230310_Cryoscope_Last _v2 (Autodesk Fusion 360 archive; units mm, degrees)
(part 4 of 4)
sketch "Sketch3" plane through (0, 0, 0) normal (0, 0, -1) x axis (1, 0, 0)
  line L1 (1.15, 0) -> (0, 0)
  circle C1 centre (0, 0) radius 3
  circle C2 centre (-1.5, 0) radius 0.35
  circle C3 centre (1.5, 0) radius 0.35
  arc A1 centre (0, 0) radius 1.5 clockwise from (1.4592, -0.3476) to (1.4592, 0.3476)
  point P1 (0, 0)
  point P3 (0, 0)
  point P4 (-1.5, 0)
  point P5 (0, 0)
  point P7 (1.4592, 0.3476)
  point P8 (1.15, 0)
  point P9 (1.4592, -0.3476)
  coincident P1 P3
  coincident P4 A1
  coincident P1 P5
  horizontal L1
  coincident C3 P7
  coincident C3 P8
  coincident C3 P9
  dimension "d8" diameter A1 = 3
  dimension "d9" diameter C2 = 0.7
  dimension "d10" diameter C3 = 0.7
extrude "Extrude3" add sketch "Sketch3" profile of A1 C2 C3 along normal blind 10
extrude "Extrude4" add of existing geometry blind 10
split "Split1"

design "Lumatec 3 mm LLG"
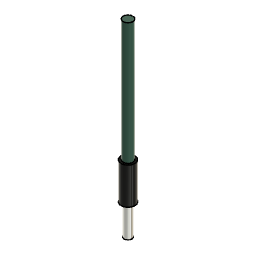
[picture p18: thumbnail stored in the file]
sketch "Sketch1" plane through (0, 0, 0) normal (0, 0, 1) x axis (1, 0, 0)
  circle C1 centre (0, 0) radius 2.46
  point P1 (0, 0)
  point P2 (0, 0)
  coincident P1 P2
  dimension "d1" diameter C1 = 4.92
extrude "Extrude1" new body sketch "Sketch1" along normal blind 20
sketch "Sketch2" plane through (0, 0, 0) normal (0, 0, -1) x axis (1, 0, 0)
  circle C1 centre (0, 0) radius 2.46
  circle C2 centre (0, 0) radius 1.5
  point P1 (0, 0)
  point P3 (0, 0)
  coincident P1 P3
  dimension "d4" diameter C2 = 3
sketch "Sketch3" plane through (0, 0, 0) normal (0, 0, -1) x axis (1, 0, 0)
  circle C1 centre (0, 0) radius 2.46
  circle C2 centre (0, 0) radius 1.5
  concentric C1 C2
  dimension "d7" diameter C2 = 3
extrude "Extrude3" cut sketch "Sketch3" profile of C2 against normal blind 31
extrude "Extrude4" new body sketch "Sketch2" profile of C2 against normal blind 20
sketch "Sketch4" plane through (0, 0, 20) normal (0, 0, 1) x axis (-1, 0, 0)
  circle C1 centre (0, 0) radius 1.5
  circle C2 centre (0, 0) radius 2.46
  circle C3 centre (0, 0) radius 4.475
  concentric C1 C3
  dimension "d12" diameter C3 = 8.95
extrude "Extrude5" new body sketch "Sketch4" along normal blind 24
extrude "Extrude6" add of existing geometry blind 24
sketch "Sketch5" plane through (0, 0, 44) normal (0, 0, 1) x axis (-1, 0, 0)
  circle C1 centre (0, 0) radius 1.5
  circle C2 centre (0, 0) radius 4.475
  circle C3 centre (0, 0) radius 3.1623
  point P1 (0, 0)
  point P3 (0, 0)
  coincident P1 P3
extrude "Extrude7" new body sketch "Sketch5" profile of C1 C3 along normal blind 80
extrude "Extrude8" add of existing geometry blind 0.1

design "Zeiss_dovetail"
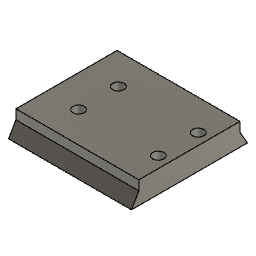
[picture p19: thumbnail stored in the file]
sketch "Sketch1" plane through (0, 0, 0) normal (1, 0, 0) x axis (0, 1, 0)
  line L1 (72.6, 0) -> (0, 0)
  line L2 (72.6, -11) -> (72.6, 0)
  line L3 (72.6, -3) -> (72.6, -11)
  line L4 (0, -11) -> (72.6, -11)
  line L5 (0, -3) -> (72.6, -3)
  line L6 (0, -11) -> (0, -3)
  line L7 (72.6, -11) -> (0, -11)
  line L8 (72.6, -3) -> (72.6, -11)
  line L9 (0, 0) -> (0, -3)
  line L10 (4.6188, -3) -> (0, -11)
  line L11 (9.2376, -11) -> (0, -11)
  line L12 (67.9812, -3) -> (72.6, -11)
  line L13 (78.8376, -11) -> (72.6, -11)
  line L14 (4.6188, 0) -> (4.6188, -3)
  line L15 (67.9812, 0) -> (67.9812, -3)
  point P1 (0, 0)
  point P2 (0, 0)
  point P9 (0, 0)
  point P10 (4.6188, -3)
  point P12 (67.9812, -3)
  point P14 (4.6188, 0)
  point P15 (67.9812, 0)
  point P3 (72.6, 0)
  point P4 (72.6, -11)
  point P5 (72.6, -3)
  coincident P1 P2
  horizontal L1
  perpendicular L1 L2
  perpendicular L1 L3
  perpendicular L3 L4
  horizontal L5
  vertical L6
  horizontal L7
  vertical L8
  coincident P1 P9
  perpendicular L1 L9
  horizontal L11
  coincident L5 P10
  horizontal L13
  coincident L5 P12
  coincident L1 P14
  perpendicular L1 L14
  coincident L1 P15
  perpendicular L1 L15
  dimension "d1" distance P2 P3 = 72.6
  dimension "d2" distance P3 P4 = 11
  dimension "d3" distance P4 P5 = 8
  dimension "d4" angle L10 L11 = 60
  dimension "d5" angle L12 L13 = 120
extrude "Extrude1" new body sketch "Sketch1" profile of L1 L4 L5 L7 L10 L12 L14 L15 along normal blind 70
sketch "Sketch2" plane through (0, 0, -11) normal (0, 0, -1) x axis (1, 0, 0)
  line L1 (0, -72.6) -> (0, 0)
  line L2 (70, -72.6) -> (0, -72.6)
  line L3 (70, 0) -> (70, -72.6)
  line L4 (0, 0) -> (70, 0)
  line L5 (70, -72.6) -> (70, 0)
  line L6 (0, -36.3) -> (70, -36.3)
  line L7 (70, -23.8) -> (70, -36.3)
  line L8 (0, -23.8) -> (70, -23.8)
  line L9 (70, -48.8) -> (70, -36.3)
  line L10 (0, -48.8) -> (70, -48.8)
  line L11 (60, -36.3) -> (35, -36.3)
  line L12 (10, -36.3) -> (35, -36.3)
  line L13 (10, -48.8) -> (10, -36.3)
  line L14 (10, -23.8) -> (10, -36.3)
  line L15 (60, -23.8) -> (60, -36.3)
  line L16 (60, -48.8) -> (60, -36.3)
  circle C1 centre (60, -48.8) radius 3.5
  circle C2 centre (60, -23.8) radius 3.5
  circle C3 centre (10, -48.8) radius 3.5
  circle C4 centre (10, -23.8) radius 3.5
  point P5 (70, 0)
  point P6 (70, 0)
  point P4 (70, -72.6)
  point P7 (70, -72.6)
  point P8 (70, -36.3)
  point P9 (0, -36.3)
  point P11 (0, -23.8)
  point P12 (70, -48.8)
  point P13 (0, -48.8)
  point P14 (35, -36.3)
  point P17 (10, -48.8)
  point P18 (10, -23.8)
  point P19 (60, -23.8)
  point P20 (60, -48.8)
  point P21 (60, -48.8)
  point P22 (60, -23.8)
  point P23 (10, -48.8)
  point P24 (10, -23.8)
  point P10 (70, -23.8)
  point P15 (60, -36.3)
  point P16 (10, -36.3)
  coincident P5 P6
  coincident P4 P7
  midpoint L5 P8
  midpoint L1 P9
  perpendicular L6 L7
  coincident L1 P11
  perpendicular L1 L8
  coincident L5 P12
  coincident L1 P13
  perpendicular L1 L10
  midpoint L6 P14
  parallel L6 L11
  parallel L6 L12
  coincident L10 P17
  perpendicular L10 L13
  coincident L8 P18
  perpendicular L8 L14
  coincident L8 P19
  perpendicular L8 L15
  coincident L10 P20
  perpendicular L10 L16
  coincident P20 P21
  coincident P19 P22
  coincident P17 P23
  coincident P18 P24
  dimension "d8" distance P8 P10 = 12.5
  dimension "d9" distance P8 P12 = 12.5
  dimension "d10" distance P14 P15 = 25
  dimension "d11" distance P14 P16 = 25
  dimension "d12" diameter C1 = 7
  dimension "d13" diameter C2 = 7
  dimension "d14" diameter C3 = 7
  dimension "d15" diameter C4 = 7
extrude "Extrude2" cut sketch "Sketch2" profile of L8 L10 L13 L14 L15 L16 C1 C2 C3 C4 against normal blind 100
sketch "Sketch3" plane through (0, 0, -11) normal (0, 0, -1) x axis (1, 0, 0)
  line L1 (0, -72.6) -> (0, 0)
  line L2 (70, -72.6) -> (0, -72.6)
  line L3 (70, 0) -> (70, -72.6)
  line L4 (0, 0) -> (70, 0)
  circle C1 centre (60, -48.8) radius 3.5
  circle C2 centre (10, -48.8) radius 3.5
  circle C3 centre (60, -23.8) radius 3.5
  circle C4 centre (10, -23.8) radius 3.5
  circle C5 centre (60, -23.8) radius 5
  circle C6 centre (60, -48.8) radius 5
  circle C7 centre (10, -48.8) radius 5
  circle C8 centre (10, -23.8) radius 5
  concentric C3 C5
  concentric C1 C6
  concentric C2 C7
  concentric C4 C8
  dimension "d18" diameter C5 = 10
  dimension "d19" diameter C6 = 10
  dimension "d20" diameter C7 = 10
  dimension "d21" diameter C8 = 10
extrude "Extrude3" cut sketch "Sketch3" profile of C1 C2 C3 C4 C5 C6 C7 C8 against normal blind 6
extrude "Extrude4" add of existing geometry blind 10
extrude "Extrude5" add of existing geometry blind 10
extrude "Extrude6" cut of existing geometry blind -13
extrude "Extrude7" add of existing geometry blind 3

design "PH50E_M-Step"
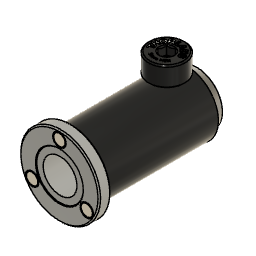
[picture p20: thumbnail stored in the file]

design "C60-TUBE-B (CATALOG MODEL)"
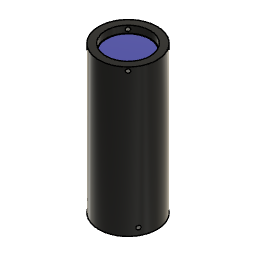
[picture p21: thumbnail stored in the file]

design "USB_A_FEM" references "BOOMELE(Boom Precision Elec) C32896"
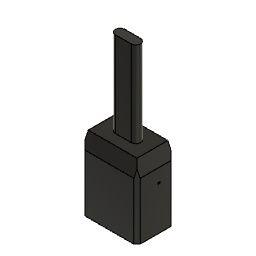
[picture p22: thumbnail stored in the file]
component_insert "Component Insert"
sketch "Sketch1" plane through (0, 0, 0) normal (0, 0, -1) x axis (1, 0, 0)
  line L1 (-6.75, 1.85) -> (-6.55, 1.85)
  line L2 (-7.15, -1.45) -> (-7.15, 1.45)
  line L3 (-6.55, -1.85) -> (-6.75, -1.85)
  line L4 (-6.55, -2.45) -> (-6.55, -1.85)
  line L5 (-5.65, -2.85) -> (-6.15, -2.85)
  line L6 (-5.65, -2.95) -> (-5.65, -2.85)
  line L7 (5.25, -3.35) -> (-5.25, -3.35)
  line L8 (5.65, -2.85) -> (5.65, -2.95)
  line L9 (6.15, -2.85) -> (5.65, -2.85)
  line L10 (6.55, -1.85) -> (6.55, -2.45)
  line L11 (6.75, -1.85) -> (6.55, -1.85)
  line L12 (7.15, 1.45) -> (7.15, -1.45)
  line L13 (6.55, 1.85) -> (6.75, 1.85)
  line L14 (6.55, 2.45) -> (6.55, 1.85)
  line L15 (5.65, 2.85) -> (6.15, 2.85)
  line L16 (5.65, 2.95) -> (5.65, 2.85)
  line L17 (-5.25, 3.35) -> (5.25, 3.35)
  line L18 (-5.65, 2.85) -> (-5.65, 2.95)
  line L19 (-6.15, 2.85) -> (-5.65, 2.85)
  line L20 (-6.55, 1.85) -> (-6.55, 2.45)
  line L21 (6.15, -2.05) -> (6.15, 2.05)
  line L22 (-5.75, -2.45) -> (5.75, -2.45)
  line L23 (-6.15, 2.05) -> (-6.15, -2.05)
  line L24 (5.75, 2.45) -> (-5.75, 2.45)
  line L25 (-8.7, 5.85) -> (8.7, 5.85)
  line L26 (-8.7, -5.85) -> (-8.7, 5.85)
  line L27 (8.7, -5.85) -> (-8.7, -5.85)
  line L28 (8.7, 5.85) -> (8.7, -5.85)
  line L29 (-8.7, -5.85) -> (8.7, 5.85)
  line L30 (8.7, -5.85) -> (-8.7, 5.85)
  arc A1 centre (-6.75, 1.45) radius 0.4 clockwise from (-7.15, 1.45) to (-6.75, 1.85)
  arc A2 centre (-6.75, -1.45) radius 0.4 clockwise from (-6.75, -1.85) to (-7.15, -1.45)
  arc A3 centre (-6.15, -2.45) radius 0.4 clockwise from (-6.15, -2.85) to (-6.55, -2.45)
  arc A4 centre (-5.25, -2.95) radius 0.4 clockwise from (-5.25, -3.35) to (-5.65, -2.95)
  arc A5 centre (5.25, -2.95) radius 0.4 clockwise from (5.65, -2.95) to (5.25, -3.35)
  arc A6 centre (6.15, -2.45) radius 0.4 clockwise from (6.55, -2.45) to (6.15, -2.85)
  arc A7 centre (6.75, -1.45) radius 0.4 clockwise from (7.15, -1.45) to (6.75, -1.85)
  arc A8 centre (6.75, 1.45) radius 0.4 clockwise from (6.75, 1.85) to (7.15, 1.45)
  arc A9 centre (6.15, 2.45) radius 0.4 clockwise from (6.15, 2.85) to (6.55, 2.45)
  arc A10 centre (5.25, 2.95) radius 0.4 clockwise from (5.25, 3.35) to (5.65, 2.95)
  arc A11 centre (-5.25, 2.95) radius 0.4 clockwise from (-5.65, 2.95) to (-5.25, 3.35)
  arc A12 centre (-6.15, 2.45) radius 0.4 clockwise from (-6.55, 2.45) to (-6.15, 2.85)
  arc A13 centre (5.75, -2.05) radius 0.4 clockwise from (6.15, -2.05) to (5.75, -2.45)
  arc A14 centre (-5.75, -2.05) radius 0.4 clockwise from (-5.75, -2.45) to (-6.15, -2.05)
  arc A15 centre (-5.75, 2.05) radius 0.4 clockwise from (-6.15, 2.05) to (-5.75, 2.45)
  arc A16 centre (5.75, 2.05) radius 0.4 clockwise from (5.75, 2.45) to (6.15, 2.05)
  point P62 (0, 0)
  point P1 (0, 0)
  point P60 (-8.7, -5.85)
  point P61 (8.7, -5.85)
  point P59 (-8.7, 5.85)
  horizontal L25
  perpendicular L25 L26
  parallel L25 L27
  parallel L26 L28
  coincident L29 P62
  coincident L30 P62
  coincident P1 P62
  dimension "d1" distance P60 P61 = 17.4
  dimension "d2" distance P59 P60 = 11.7
extrude "Extrude1" new body sketch "Sketch1" profile of L1 A1 L2 A2 L3 L4 A3 L5 L6 A4 L7 A5 L8 L9 A6 L10 L11 A7 L12 A8 L13 L14 A9 L15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 against normal blind 18
sketch "Sketch2" plane through (0, 0, 18) normal (0, 0, 1) x axis (-1, 0, 0)
  line L1 (6.55, 1.85) -> (6.55, 2.45)
  line L2 (6.75, 1.85) -> (6.55, 1.85)
  line L3 (7.15, -1.45) -> (7.15, 1.45)
  line L4 (6.55, -1.85) -> (6.75, -1.85)
  line L5 (6.55, -2.45) -> (6.55, -1.85)
  line L6 (5.65, -2.85) -> (6.15, -2.85)
  line L7 (5.65, -2.95) -> (5.65, -2.85)
  line L8 (-5.25, -3.35) -> (5.25, -3.35)
  line L9 (-5.65, -2.85) -> (-5.65, -2.95)
  line L10 (-6.15, -2.85) -> (-5.65, -2.85)
  line L11 (-6.55, -1.85) -> (-6.55, -2.45)
  line L12 (-6.75, -1.85) -> (-6.55, -1.85)
  line L13 (-7.15, 1.45) -> (-7.15, -1.45)
  line L14 (-6.55, 1.85) -> (-6.75, 1.85)
  line L15 (-6.55, 2.45) -> (-6.55, 1.85)
  line L16 (-5.65, 2.85) -> (-6.15, 2.85)
  line L17 (-5.65, 2.95) -> (-5.65, 2.85)
  line L18 (5.25, 3.35) -> (-5.25, 3.35)
  line L19 (5.65, 2.85) -> (5.65, 2.95)
  line L20 (6.15, 2.85) -> (5.65, 2.85)
  line L21 (-8.7, -5.85) -> (-8.7, 5.85)
  line L22 (8.7, -5.85) -> (-8.7, -5.85)
  line L23 (8.7, 5.85) -> (8.7, -5.85)
  line L24 (-8.7, 5.85) -> (8.7, 5.85)
  line L25 (7.7, 4.85) -> (-7.7, 4.85)
  line L26 (7.7, -4.85) -> (7.7, 4.85)
  line L27 (-7.7, -4.85) -> (7.7, -4.85)
  line L28 (-7.7, 4.85) -> (-7.7, -4.85)
  line L29 (7.7, -4.85) -> (-7.7, 4.85)
  line L30 (-7.7, -4.85) -> (7.7, 4.85)
  arc A1 centre (6.75, 1.45) radius 0.4 clockwise from (6.75, 1.85) to (7.15, 1.45)
  arc A2 centre (6.75, -1.45) radius 0.4 clockwise from (7.15, -1.45) to (6.75, -1.85)
  arc A3 centre (6.15, -2.45) radius 0.4 clockwise from (6.55, -2.45) to (6.15, -2.85)
  arc A4 centre (5.25, -2.95) radius 0.4 clockwise from (5.65, -2.95) to (5.25, -3.35)
  arc A5 centre (-5.25, -2.95) radius 0.4 clockwise from (-5.25, -3.35) to (-5.65, -2.95)
  arc A6 centre (-6.15, -2.45) radius 0.4 clockwise from (-6.15, -2.85) to (-6.55, -2.45)
  arc A7 centre (-6.75, -1.45) radius 0.4 clockwise from (-6.75, -1.85) to (-7.15, -1.45)
  arc A8 centre (-6.75, 1.45) radius 0.4 clockwise from (-7.15, 1.45) to (-6.75, 1.85)
  arc A9 centre (-6.15, 2.45) radius 0.4 clockwise from (-6.55, 2.45) to (-6.15, 2.85)
  arc A10 centre (-5.25, 2.95) radius 0.4 clockwise from (-5.65, 2.95) to (-5.25, 3.35)
  arc A11 centre (5.25, 2.95) radius 0.4 clockwise from (5.25, 3.35) to (5.65, 2.95)
  arc A12 centre (6.15, 2.45) radius 0.4 clockwise from (6.15, 2.85) to (6.55, 2.45)
  point P54 (0, 0)
  point P1 (0, 0)
  point P52 (7.7, -4.85)
  point P53 (-7.7, -4.85)
  point P51 (7.7, 4.85)
  horizontal L25
  perpendicular L25 L26
  parallel L25 L27
  parallel L26 L28
  coincident L29 P54
  coincident L30 P54
  coincident P1 P54
  dimension "d5" distance P52 P53 = 15.4 (= "17.400 mm - 2 mm")
  dimension "d6" distance P51 P52 = 9.7 (= "11.700 mm - 2 mm")
extrude "Extrude2" add sketch "Sketch2" profile of L1 L2 A1 L3 A2 L4 L5 A3 L6 L7 A4 L8 A5 L9 L10 A6 L11 L12 A7 L13 A8 L14 L15 A9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 along normal blind 5
chamfer "Chamfer1" distance 1 distance 5
sketch "Sketch3" plane through (0, 0, 23) normal (0, 0, 1) x axis (-1, 0, 0)
  line L1 (7.7, -4.85) -> (-7.7, -4.85)
  line L2 (7.7, 4.85) -> (7.7, -4.85)
  line L3 (-7.7, 4.85) -> (7.7, 4.85)
  line L4 (-7.7, -4.85) -> (-7.7, 4.85)
  line L5 (-2.5, 0) -> (0, 0)
  line L6 (2.5, 0) -> (-2.5, 0)
  line L7 (2.5, -1.5) -> (-2.5, -1.5)
  line L8 (-2.5, 1.5) -> (2.5, 1.5)
  line L9 (2.5, 0) -> (-2.5, 0)
  arc A1 centre (2.5, 0) radius 1.5 clockwise from (2.5, 1.5) to (2.5, -1.5)
  arc A2 centre (-2.5, 0) radius 1.5 clockwise from (-2.5, -1.5) to (-2.5, 1.5)
  point P1 (0, 0)
  point P6 (0, 0)
  point P8 (2.5, 0)
  point P14 (2.5, 0)
  point P7 (-2.5, 0)
  point P13 (-2.5, 0)
  coincident P1 P6
  horizontal L5
  parallel L5 L6
  tangent L7 A1
  tangent A1 L8
  parallel L7 L8
  tangent L8 A2
  tangent L7 A2
  coincident P8 P14
  parallel L6 L9
  coincident P7 P13
  dimension "d11" distance P6 P7 = 2.5
  dimension "d12" distance P7 P8 = 5
  dimension "d13" diameter A1 = 3
extrude "Extrude3" add sketch "Sketch3" profile of L7 A1 L8 A2 along normal blind 27
chamfer "Chamfer2" distance 1

design "B6090L-Step (1)"
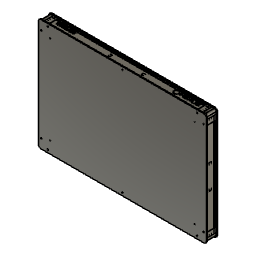
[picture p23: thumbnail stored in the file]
